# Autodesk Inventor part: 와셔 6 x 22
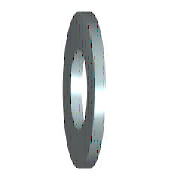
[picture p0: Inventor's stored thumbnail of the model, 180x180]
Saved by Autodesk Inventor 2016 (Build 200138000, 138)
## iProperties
Created: 2012-02
Part Number: 와셔 6 x 22
Material: 강철
Description: 평면 와셔 - 초대형 시리즈 - 제품 등급 C
Document SubType Name: Modeling
Standard: ISO 7094
Designer: mdu-01
Standard Revision: Second edition 2000-06-01
Standards Organization: ISO
Language: ko-KR
Size Designation: ST 6 - 100 HV
Categories: <MemberInstance><Categories><Category DisplayName="조임쇠" InternalName="e4da775c-781d-43d5-af7c-5136215cf5a6" Mnemonic="FSTN"><Category DisplayName="와셔" InternalN
Density: 7.85 g/cm^3
Appearance: 파란색 - 벽 페인트 - 광택
IsCustomPart: 1
Author: mdu-01
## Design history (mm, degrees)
sketch "스케치"
  geometry: C1 r 11 at (0, 0); C2 r 3.3 at (0, 0); 1 further point
  constraints: 2 centre point, 2 coincident
  dimensions: "d0" = 6.6 diameter of C2 (= SD1); "d1" = 22 diameter of C1 (= SD2)
extrude "본체" new body sketch "스케치" distance "d2" = 2 (= SD); taper "d3" = 0 deg
workaxis "Work Axis1"
workplane "Work Plane1"
body "Solid1"
other parameters: "SD1" = 6.6 [user parameter; used in 1 equation term], "SD2" = 22 [user parameter; used in 1 equation term], "SD" = 2 [user parameter; used in 1 equation term], "d4" = 0, "d5" = 0, "d6" = 0, "d7" = 0, "NND" = 6 [user parameter]
